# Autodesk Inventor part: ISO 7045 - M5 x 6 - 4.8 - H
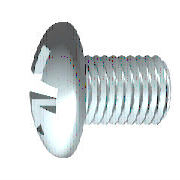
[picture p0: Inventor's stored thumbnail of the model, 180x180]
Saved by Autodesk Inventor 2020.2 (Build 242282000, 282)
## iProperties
Manager: www.cadconsulting.pl
Company: Fabian Stasiak CAD Consulting
Created: 2016-02
Part Number: ISO 7045 - M5 x 6 - 4.8 - H
Material: Stal
Description: Śruba z łbem walcowym wypukłym z wgłębieniem krzyżowym
Document SubType Name: Modeling
Standard: DIN EN ISO 7045
Designer: F.Stasiak
Standard Revision: 2011-12
Standards Organization: DIN
Language: pl-PL
Size Designation: M5 x 6 - 4.8 - H
Categories: <MemberInstance><Categories><Category DisplayName="Mocowania" InternalName="e4da775c-781d-43d5-af7c-5136215cf5a6" Mnemonic="FSTN"><Category DisplayName="Śruby"
Density: 7.85 g/cm^3
Appearance: Płyta
IsCustomPart: 0
Author: F.Stasiak
Subject: Zbiór ćwiczeń. Autodesk Inventor 2020. Kurs podstawowy
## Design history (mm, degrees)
workplane "Work Plane3"
sketch "Szkic2"
  geometry: L1 (-6.543, 0)-(6.543, 0) reference; L2 (0, -6.543)-(0, 6.543) reference; L3 (0, 2.45)-(0, 0); L4 (0, 0)-(2.45, 0); L5 (0, 0)-(3.305, 3.305); L6 (0.415, 2.415)-(0.426, 0.744); L7 (2.415, 0.415)-(0.744, 0.426); L8 (0.415, -2.415)-(0.426, -0.744); L9 (2.415, -0.415)-(0.744, -0.426); L10 (-0.415, 2.415)-(-0.426, 0.744); L11 (-2.415, 0.415)-(-0.744, 0.426); L12 (-2.415, -0.415)-(-0.744, -0.426); L13 (-0.415, -2.415)-(-0.426, -0.744); A1 r 0.735 centre (0, 0) between (0.735, 0) and (0, 0.735); A2 r 2.45 centre (0, 0) between (2.45, 0) and (2.415, 0.415); A3 r 2.45 centre (0, 0) between (0.415, 2.415) and (0, 2.45); A4 r 2.45 centre (0, 0) between (2.415, 0.415) and (0.415, 2.415); A5 r 2.45 centre (0, 0) between (0, -2.45) and (0.415, -2.415); A6 r 2.45 centre (0, 0) between (0.415, -2.415) and (2.415, -0.415); A7 r 2.45 centre (0, 0) between (2.415, -0.415) and (2.45, 0); A8 r 2.45 centre (0, 0) between (-2.415, 0.415) and (-2.45, 0); A9 r 2.45 centre (0, 0) between (-0.415, 2.415) and (-2.415, 0.415); A10 r 2.45 centre (0, 0) between (0, 2.45) and (-0.415, 2.415); A11 r 2.45 centre (0, 0) between (-2.45, 0) and (-2.415, -0.415); A12 r 2.45 centre (0, 0) between (-2.415, -0.415) and (-0.415, -2.415); A13 r 2.45 centre (0, 0) between (-0.415, -2.415) and (0, -2.45); A14 r 0.858 centre (0, 0) between (0.858, 0) and (0, 0.858); A15 r 0.321 centre (0.746, 0.746) between (0.426, 0.744) and (0.744, 0.426); A16 r 0.321 centre (0.746, -0.746) between (0.744, -0.426) and (0.426, -0.744); A17 r 0.321 centre (-0.746, 0.746) between (-0.744, 0.426) and (-0.426, 0.744); A18 r 0.321 centre (-0.746, -0.746) between (-0.426, -0.744) and (-0.744, -0.426); 1 further point
  constraints: 38 point on circle, 22 end point, 19 symmetric about line, 18 centre point, 4 coincident, 3 collinear, 3 point on line, 3 tangent, 1 perpendicular, 21 other
  dimensions: "d4" = 45 deg angle of L5 L4; "d5" = 1.47 diameter of A1 (= 0.3 x SDM); "d6" = 4.9 diameter of A4 (= SDM); "d7" = 0.415 distance from line of L6.start L3 (= 0.5 x SBR); "d14" = 1.715 diameter of A14 (= 0.35 x SDM)
extrude "Szczelina" join sketch "Szkic2" taper "d15" = 5 deg; stored distance "d54" = 10
revolve "Wycięcie" stored, may be unused: angle "d56" = 90 deg
revolve "Bryła" stored, may be unused: angle "d18" = 90 deg
workplane "Work Plane1"
body "Solid1"
sketch "Szkic1"
  geometry: L1 (6, 0)-(6, 2.5); L2 (6, 2.5)-(1.6, 2.5); L3 (3.962, 5.08)-(3.962, 5.08); L4 (-3.7, 0)-(-3.7, 4.621); L5 (-3.367, 2.284)-(-1.526, 1.366); L6 (-1.526, 1.366)-(-0.8, 0); L7 (-0.8, 0)-(6, 0); L8 (-6.081, 0)-(8.013, 0) reference; L9 (0, -1.016)-(0, 6.096) reference; L10 (-3.367, 2.284)-(-3.7, 2.45); L11 (-2.193, 4.673)-(-3.7, 4.621); L12 (-2.193, 4.673)-(0, 4.75); L13 (0, 4.75)-(0, 2.483); L14 (0.2, 2.283)-(1.109, 2.283); L15 (1.109, 2.283)-(1.6, 2.5); L16 (1.6, 2.5)-(0, 2.5); A1 r 8 centre (4.3, 0) between (-2.193, 4.673) and (-3.7, 0); A2 r 0.2 centre (0.2, 2.483) between (0, 2.483) and (0.2, 2.283); 1 further point
  constraints: 28 end point, 7 point on line, 6 point on circle, 4 collinear, 3 parallel, 3 tangent, 2 centre point, 2 perpendicular, 1 horizontal
  dimensions: "d1" = 5 diameter of L2 L7 (= GD); "d2" = 2.9 distance from line of L6.end L4 (= STI); "d11" = 4.9 diameter of L10.end L7 (= SDM); "d12" = 62 deg angle of L6 L7; "d13" = 26.5 deg angle of L5 L7; "d17" = 9.5 diameter of L12.end L7 (= KOD); "d19" = 2 deg angle of L12 L7 (= KEWI); "d20" = 3.7 distance between parallel lines of L4 L13 (= KOH); "d21" = 8 radius of A1 (= KR); "d23" = 4.56699 diameter of L14 L7 (= BDM); "d24" = 4.4 distance of L1.end L2.end (= GEL); "d25" = 0.49076 horizontal distance of L14.end L2.end (= GAL); "d28" = 6 distance between parallel lines of L1 L13 (= NLG); "d81" = 0.2 radius of A2 (= R)
fillet "Zaokrąglenie1" dims "d29" = 1.6 (= RR)
fillet "Zaokrąglenie2" dims "d16" = 0.166 (= 0.2 x SBR)
feature "Gwint" dims "d8" = 4.4 (= GEL), "d9" = 0
chamfer "Faza1" distance "d26" = 0.49076 (= -0.5 x SPD + 0.5 x GD); stored, may be unused: second distance "d27" = 0.49086 (computed from GUL), angle "d78" = 45 deg
other parameters: "GD" = 5 [user parameter; used in 2 equation terms], "NLG" = 6 [user parameter; used in 1 equation term], "GEL" = 4.4 [user parameter; used in 2 equation terms], "KOD" = 9.5 [user parameter; used in 1 equation term], "KOH" = 3.7 [user parameter; used in 2 equation terms], "SDM" = 4.9 [user parameter; used in 4 equation terms], "STI" = 2.9 [user parameter; used in 1 equation term], "SBR" = 0.83 [user parameter; used in 2 equation terms], "GAL" = 0.49076 (= 0.61345 x PTC) [user parameter; used in 1 equation term], "SPD" = 4.01848 (= NND - 1.2269 x PTC) [user parameter; used in 1 equation term], "KEWI" = 2 deg [user parameter; used in 1 equation term], "d3" = -3.7 (= -KOH), "d10" = 0, "KR" = 8 [user parameter; used in 1 equation term], "BDM" = 4.56699 [user parameter; used in 1 equation term], "GUL" = 0.49076 (= 0.61345 x PTC) [user parameter; used in 1 equation term], "RR" = 1.6 [user parameter; used in 1 equation term], "d79" = 0, "d80" = 0, "R" = 0.2 [user parameter; used in 1 equation term], "PTC" = 0.8 [user parameter; used in 5 equation terms], "THREADDIA" = 5 [user parameter; used in 1 equation term], "TOA" = 30 deg [user parameter], "TPU" = 12.5 (computed from PTC) [user parameter], "NND" = 5 [user parameter; used in 1 equation term], "GD1" = 4.01848 (= THREADDIA - 1.2269 x PTC) [user parameter]
